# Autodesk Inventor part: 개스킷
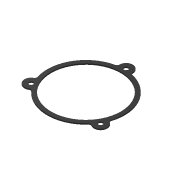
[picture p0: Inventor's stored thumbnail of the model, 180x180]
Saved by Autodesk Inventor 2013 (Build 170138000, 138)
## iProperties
Created: 2018-05
Part Number: 개스킷
Material: 고무, 실리콘
Document SubType Name: Modeling
Designer: mduedu
Density: 1 g/cm^3
Author: mduedu
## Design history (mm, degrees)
sketch "스케치1"
  geometry: L1 (0, 52)-(0, 0); L2 (0, 0)-(-45.033, -26); L3 (0, 0)-(45.033, -26); C1 r 3 at (-45.033, -26); C2 r 3 at (0, 52); C3 r 3 at (45.033, -26); C4 r 45 at (0, 0); A1 r 3 centre (-39.058, -35.826) between (-36.847, -33.798) and (-40.617, -33.262); A2 r 8.5 centre (-45.033, -26) between (-49.114, -18.544) and (-40.617, -33.262); A3 r 3 centre (-50.555, -15.912) between (-49.114, -18.544) and (-47.693, -15.012); A4 r 50 centre (0, 0) between (-10.846, 48.809) and (-47.693, -15.012); A5 r 3 centre (-11.497, 51.738) between (-10.846, 48.809) and (-8.498, 51.806); A6 r 8.5 centre (0, 52) between (8.498, 51.806) and (-8.498, 51.806); A7 r 3 centre (11.497, 51.738) between (8.498, 51.806) and (10.846, 48.809); A8 r 50 centre (0, 0) between (47.693, -15.012) and (10.846, 48.809); A9 r 3 centre (50.555, -15.912) between (47.693, -15.012) and (49.114, -18.544); A10 r 8.5 centre (45.033, -26) between (40.617, -33.262) and (49.114, -18.544); A11 r 3 centre (39.058, -35.826) between (40.617, -33.262) and (36.847, -33.798); A12 r 50 centre (0, 0) between (-36.847, -33.798) and (36.847, -33.798); 1 further point
  constraints: 24 point on circle, 16 centre point, 12 tangent, 11 equal radius, 6 concentric, 6 end point, 2 coincident, 2 equal length, 2 vertical alignment, 1 vertical
  dimensions: "d1" = 90 diameter of C4; "d3" = 50 radius of A8; "d4" = 3 radius of A7; "d5" = 8.5 radius of A6; "d6" = 120 deg angle of L2 L1; "d7" = 120 deg angle of L3 L1; "d8" = 6 diameter of C2; "d9" = 52 distance of L1.start L1.end
extrude "돌출1" new body sketch "스케치1" distance "d10" = 1.5; taper "d11" = 0 deg
node "솔리드1"
